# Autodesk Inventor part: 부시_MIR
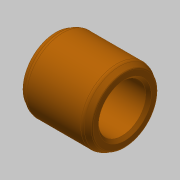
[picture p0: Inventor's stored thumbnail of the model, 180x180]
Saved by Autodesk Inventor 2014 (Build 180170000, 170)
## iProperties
Created: 2018-11
Part Number: 부시_MIR
Material: 강철, 연강
Document SubType Name: Modeling
Designer: 703
Density: 7.86 g/cm^3
Appearance: 강철
Author: mduedu
d0: 17.000 mm
d1: 26.000 mm
d2: 25.000 mm
d3: 0.00 deg
d14: 1.000 mm
d17: 2.300 mm
d19: 30.00 deg
d20: 2.300 mm
d22: 30.00 deg
d23: 2.000 mm
d24: 0.500 mm
d25: 2.000 mm
d26: 0.500 mm
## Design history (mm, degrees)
derived "부시.ipt"
  sketch "스케치1"
    geometry: C1 r 8.5 at (0, 0) reference; C2 r 13 at (0, 0) reference; 1 further point
feature "솔리드1::부시.ipt"
tag "피쳐 태그1"
node "솔리드1"
other parameters: "d0" = 10, "d0_1" = 17, "d1" = 26, "d2" = 25, "d3" = 0 deg, "d14" = 1, "d17" = 2.3, "d19" = 30 deg, "d20" = 2.3, "d22" = 30 deg, "d23" = 2, "d24" = 0.5, "d25" = 2, "d26" = 0.5
